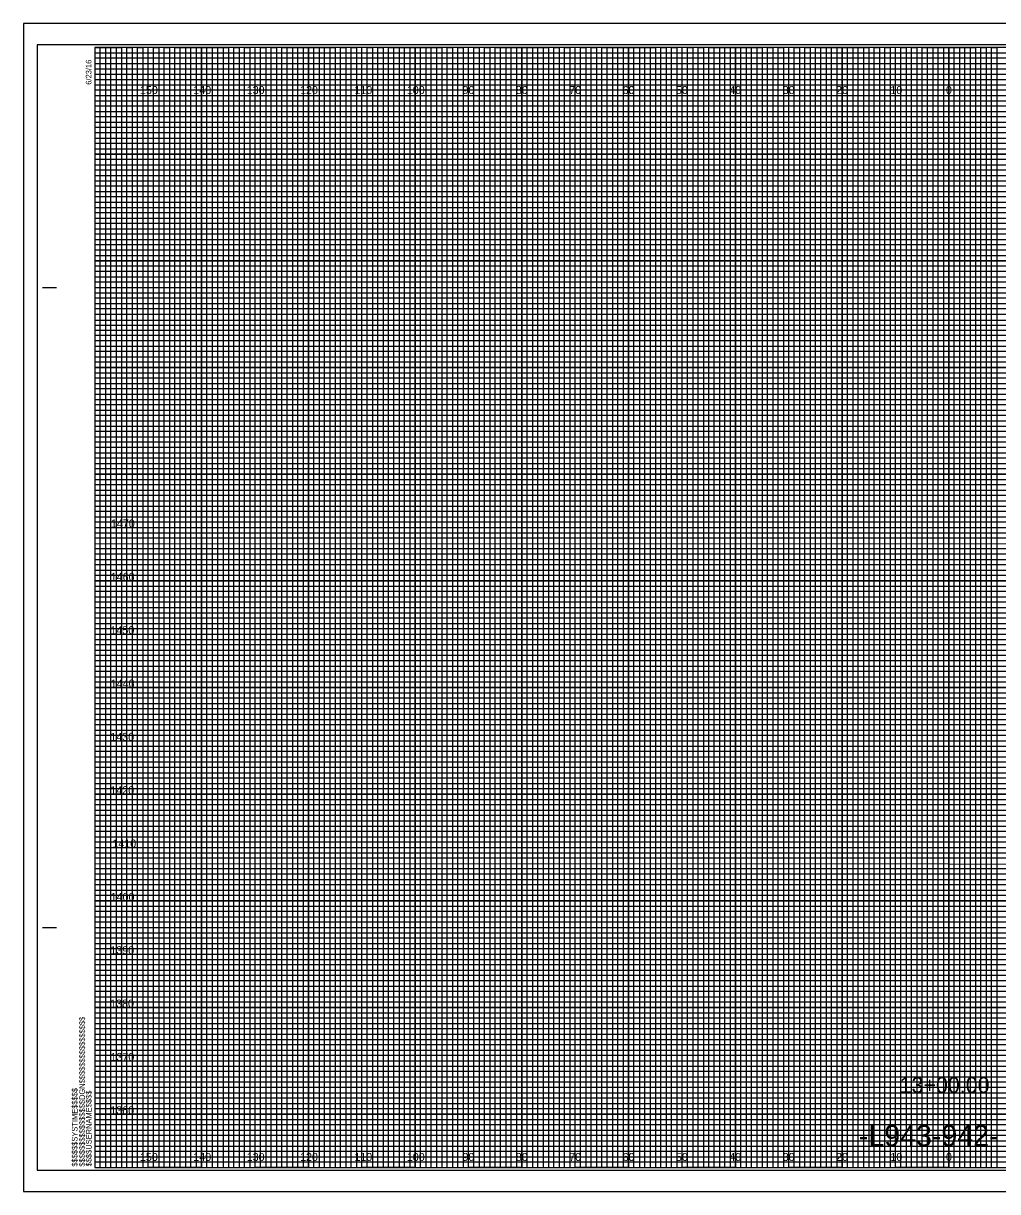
# Model space of a CAD drawing. Extents: x -13 to 323, y -5 to 215.
# Drawn here: x -13.4 to 169.1, y -4.5 to 214.5 of the extents above; entities that cross this region are included whole.
import ezdxf

# ---------------------------------------------------------------- set-up
doc = ezdxf.new("R2010")
doc.units = 0
for name, color, linetype in [('Exist Cross Section Cell', 7, 'Continuous'), ('Exist XS Center Line Elevation Label', 7, 'Continuous'), ('Exist XS Ground Line', 7, 'Continuous'), ('Prop XS EOT Tick Mark', 7, 'Continuous'), ('Prop XS Finish Grade', 7, 'Continuous'), ('Prop XS Finish Grade Earthwork', 7, 'Continuous'), ('Prop XS Finish Grade Pavement', 7, 'Continuous'), ('Prop XS Subgrade Earthwork', 7, 'Continuous'), ('Prop XSC Text', 7, 'Continuous'), ('Scratch_Level_0', 7, 'Continuous'), ('Scratch_Level_5', 7, 'Continuous'), ('Typical Curb CELL', 7, 'Continuous'), ('Typical Guardrail CELL', 7, 'Continuous')]:
    doc.layers.add(name, color=color, linetype=linetype)

msp = doc.modelspace()

# ---------------------------------------------------------------- linework, layer by layer
at = {"layer": 'Exist Cross Section Cell'}
for points in [[(0, 210), (5, 210), (5, 0), (15, 0), (15, 210), (25, 210), (25, 0), (35, 0), (35, 210), (45, 210), (45, 0), (55, 0), (55, 210), (65, 210), (65, 0), (75, 0), (75, 210), (85, 210), (85, 0), (95, 0), (95, 210), (105, 210), (105, 0), (115, 0), (115, 210), (125, 210), (125, 0), (135, 0), (135, 210), (145, 210), (145, 0), (155, 0), (155, 210), (165, 210), (165, 0), (175, 0)], [(0, 205), (275, 205)], [(0, 185), (320, 185), (320, 195), (0, 195)], [(0, 165), (320, 165), (320, 175), (0, 175)], [(0, 145), (320, 145), (320, 155), (0, 155)], [(0, 125), (320, 125), (320, 135), (0, 135)], [(0, 105), (320, 105), (320, 115), (0, 115)], [(0, 85), (320, 85), (320, 95), (0, 95)], [(0, 65), (320, 65), (320, 75), (0, 75)], [(0, 45), (320, 45), (320, 55), (0, 55)], [(0, 25), (320, 25), (320, 35), (0, 35)], [(0, 5), (320, 5), (320, 15), (0, 15)]]:
    msp.add_lwpolyline(points, dxfattribs=at)
at = {"layer": 'Exist XS Center Line Elevation Label'}
for p, q in [((10, 210), (0, 210)), ((10, 0), (10, 210)), ((30, 210), (20, 210)), ((20, 210), (20, 0)), ((30, 0), (30, 210)), ((50, 210), (40, 210)), ((40, 210), (40, 0)), ((50, 0), (50, 210)), ((70, 210), (60, 210)), ((60, 210), (60, 0)), ((70, 0), (70, 210)), ((90, 210), (80, 210)), ((80, 210), (80, 0)), ((90, 0), (90, 210)), ((110, 210), (100, 210)), ((100, 210), (100, 0)), ((110, 0), (110, 210)), ((130, 210), (120, 210)), ((120, 210), (120, 0)), ((130, 0), (130, 210)), ((150, 210), (140, 210)), ((140, 210), (140, 0)), ((150, 0), (150, 210)), ((170, 210), (160, 210)), ((160, 210), (160, 0)), ((20, 0), (10, 0)), ((40, 0), (30, 0)), ((60, 0), (50, 0)), ((80, 0), (70, 0)), ((100, 0), (90, 0)), ((120, 0), (110, 0)), ((140, 0), (130, 0)), ((160, 0), (150, 0))]:
    msp.add_line(p, q, dxfattribs=at)
for points in [[(0, 200), (320, 200), (320, 190), (0, 190)], [(0, 180), (320, 180), (320, 170), (0, 170)], [(0, 160), (320, 160), (320, 150), (0, 150)], [(0, 140), (320, 140), (320, 130), (0, 130)], [(0, 120), (320, 120), (320, 110), (0, 110)], [(0, 100), (320, 100), (320, 90), (0, 90)], [(0, 80), (320, 80), (320, 70), (0, 70)], [(0, 60), (320, 60), (320, 50), (0, 50)], [(0, 40), (320, 40), (320, 30), (0, 30)], [(0, 20), (320, 20), (320, 10), (0, 10)]]:
    msp.add_lwpolyline(points, dxfattribs=at)
at = {"layer": 'Prop XS EOT Tick Mark'}
for p, q in [((10, 0), (10, 210)), ((20, 0), (20, 210)), ((30, 0), (30, 210)), ((40, 0), (40, 210)), ((50, 0), (50, 210)), ((60, 0), (60, 210)), ((70, 0), (70, 210)), ((80, 0), (80, 210)), ((90, 0), (90, 210)), ((100, 0), (100, 210)), ((110, 0), (110, 210)), ((120, 0), (120, 210)), ((130, 0), (130, 210)), ((140, 0), (140, 210)), ((150, 0), (150, 210)), ((160, 0), (160, 210)), ((0, 200), (320, 200)), ((0, 190), (320, 190)), ((0, 180), (320, 180)), ((0, 170), (320, 170)), ((0, 160), (320, 160)), ((0, 150), (320, 150)), ((0, 140), (320, 140)), ((0, 130), (320, 130)), ((0, 120), (320, 120)), ((0, 110), (320, 110)), ((0, 100), (320, 100)), ((0, 90), (320, 90)), ((0, 80), (320, 80)), ((0, 70), (320, 70)), ((0, 60), (320, 60)), ((0, 50), (320, 50)), ((0, 40), (320, 40)), ((0, 30), (320, 30)), ((0, 20), (320, 20)), ((0, 10), (320, 10))]:
    msp.add_line(p, q, dxfattribs=at)
at = {"layer": 'Prop XS Finish Grade Pavement'}
msp.add_lwpolyline([(-13.4, -4.5), (323.3, -4.5), (323.3, 214.5), (-13.4, 214.5)], close=True, dxfattribs=at)
at = {"layer": 'Prop XS Subgrade Earthwork'}
msp.add_lwpolyline([(-10.8, -0.5), (322.4, -0.5), (322.4, 210.5), (-10.8, 210.5)], close=True, dxfattribs=at)
at = {"layer": 'Prop XSC Text'}
for points in [[(0, 0), (1, 0), (1, 210), (2, 210), (2, 0)], [(2, 0), (3, 0), (3, 210), (4, 210), (4, 0)], [(5, 0), (6, 0), (6, 210), (7, 210), (7, 0)], [(7, 0), (8, 0), (8, 210), (9, 210), (9, 0)], [(10, 0), (11, 0), (11, 210), (12, 210), (12, 0)], [(12, 0), (13, 0), (13, 210), (14, 210), (14, 0)], [(15, 0), (16, 0), (16, 210), (17, 210), (17, 0)], [(17, 0), (18, 0), (18, 210), (19, 210), (19, 0)], [(20, 0), (21, 0), (21, 210), (22, 210), (22, 0)], [(22, 0), (23, 0), (23, 210), (24, 210), (24, 0)], [(25, 0), (26, 0), (26, 210), (27, 210), (27, 0)], [(27, 0), (28, 0), (28, 210), (29, 210), (29, 0)], [(30, 0), (31, 0), (31, 210), (32, 210), (32, 0)], [(32, 0), (33, 0), (33, 210), (34, 210), (34, 0)], [(35, 0), (36, 0), (36, 210), (37, 210), (37, 0)], [(37, 0), (38, 0), (38, 210), (39, 210), (39, 0)], [(40, 0), (41, 0), (41, 210), (42, 210), (42, 0)], [(42, 0), (43, 0), (43, 210), (44, 210), (44, 0)], [(45, 0), (46, 0), (46, 210), (47, 210), (47, 0)], [(47, 0), (48, 0), (48, 210), (49, 210), (49, 0)], [(50, 0), (51, 0), (51, 210), (52, 210), (52, 0)], [(52, 0), (53, 0), (53, 210), (54, 210), (54, 0)], [(55, 0), (56, 0), (56, 210), (57, 210), (57, 0)], [(57, 0), (58, 0), (58, 210), (59, 210), (59, 0)], [(60, 0), (61, 0), (61, 210), (62, 210), (62, 0)], [(62, 0), (63, 0), (63, 210), (64, 210), (64, 0)], [(65, 0), (66, 0), (66, 210), (67, 210), (67, 0)], [(67, 0), (68, 0), (68, 210), (69, 210), (69, 0)], [(70, 0), (71, 0), (71, 210), (72, 210), (72, 0)], [(72, 0), (73, 0), (73, 210), (74, 210), (74, 0)], [(75, 0), (76, 0), (76, 210), (77, 210), (77, 0)], [(77, 0), (78, 0), (78, 210), (79, 210), (79, 0)], [(80, 0), (81, 0), (81, 210), (82, 210), (82, 0)], [(82, 0), (83, 0), (83, 210), (84, 210), (84, 0)], [(85, 0), (86, 0), (86, 210), (87, 210), (87, 0)], [(87, 0), (88, 0), (88, 210), (89, 210), (89, 0)], [(90, 0), (91, 0), (91, 210), (92, 210), (92, 0)], [(92, 0), (93, 0), (93, 210), (94, 210), (94, 0)], [(95, 0), (96, 0), (96, 210), (97, 210), (97, 0)], [(97, 0), (98, 0), (98, 210), (99, 210), (99, 0)], [(100, 0), (101, 0), (101, 210), (102, 210), (102, 0)], [(102, 0), (103, 0), (103, 210), (104, 210), (104, 0)], [(105, 0), (106, 0), (106, 210), (107, 210), (107, 0)], [(107, 0), (108, 0), (108, 210), (109, 210), (109, 0)], [(110, 0), (111, 0), (111, 210), (112, 210), (112, 0)], [(112, 0), (113, 0), (113, 210), (114, 210), (114, 0)], [(115, 0), (116, 0), (116, 210), (117, 210), (117, 0)], [(117, 0), (118, 0), (118, 210), (119, 210), (119, 0)], [(120, 0), (121, 0), (121, 210), (122, 210), (122, 0)], [(122, 0), (123, 0), (123, 210), (124, 210), (124, 0)], [(125, 0), (126, 0), (126, 210), (127, 210), (127, 0)], [(127, 0), (128, 0), (128, 210), (129, 210), (129, 0)], [(130, 0), (131, 0), (131, 210), (132, 210), (132, 0)], [(132, 0), (133, 0), (133, 210), (134, 210), (134, 0)], [(135, 0), (136, 0), (136, 210), (137, 210), (137, 0)], [(137, 0), (138, 0), (138, 210), (139, 210), (139, 0)], [(140, 0), (141, 0), (141, 210), (142, 210), (142, 0)], [(142, 0), (143, 0), (143, 210), (144, 210), (144, 0)], [(145, 0), (146, 0), (146, 210), (147, 210), (147, 0)], [(147, 0), (148, 0), (148, 210), (149, 210), (149, 0)], [(150, 0), (151, 0), (151, 210), (152, 210), (152, 0)], [(152, 0), (153, 0), (153, 210), (154, 210), (154, 0)], [(155, 0), (156, 0), (156, 210), (157, 210), (157, 0)], [(157, 0), (158, 0), (158, 210), (159, 210), (159, 0)], [(160, 0), (161, 0), (161, 210), (162, 210), (162, 0)], [(162, 0), (163, 0), (163, 210), (164, 210), (164, 0)], [(165, 0), (166, 0), (166, 210), (167, 210), (167, 0)], [(167, 0), (168, 0), (168, 210), (169, 210), (169, 0)]]:
    msp.add_lwpolyline(points, dxfattribs=at)
at = {"layer": 'Scratch_Level_0'}
for p, q in [((-9.8, 165), (-7.3, 165)), ((-9.7, 165), (-7.2, 165)), ((-9.8, 45), (-7.3, 45)), ((-9.7, 45), (-7.2, 45)), ((0, 0), (0, 0)), ((0, 0), (0, 0)), ((0, 0), (0, 0)), ((0, 0), (0, 0)), ((0, 0), (0, 0)), ((0, 0), (0, 0)), ((0, 0), (0, 0))]:
    msp.add_line(p, q, dxfattribs=at)
msp.add_lwpolyline([(320, 210), (0, 210), (0, 0), (320, 0)], close=True, dxfattribs=at)
at = {"layer": 'Scratch_Level_5'}
for p, q in [((0, 209), (260, 209)), ((260, 207.98), (0, 207.98)), ((0, 207.98), (0, 207)), ((0, 207), (260, 207)), ((260, 205.89), (0, 205.89)), ((0, 205.89), (0, 204)), ((0, 204), (320, 204))]:
    msp.add_line(p, q, dxfattribs=at)
for points in [[(0, 203), (270, 203), (320, 203), (320, 202), (0, 202)], [(0, 201), (320, 201), (320, 199), (0, 199)], [(0, 198), (320, 198), (320, 197), (0, 196.98)], [(0, 196), (320, 196), (320, 194), (0, 194)], [(0, 193), (320, 193), (320, 192), (0, 192)], [(0, 191), (320, 191), (320, 189), (0, 189)], [(0, 188), (320, 188), (320, 187), (0, 187)], [(0, 186), (320, 186), (320, 184), (0, 184)], [(0, 183), (320, 183), (320, 182), (0, 182)], [(0, 181), (320, 181), (320, 179), (0, 179)], [(0, 178), (320, 178), (320, 177), (0, 177)], [(0, 176), (320, 176), (320, 173.95), (320, 173), (320, 172), (0, 172)], [(0, 174), (320, 174), (320, 173), (0, 173)], [(0, 171), (320, 171), (320, 169), (0, 169.03)], [(0, 169.03), (320, 169), (320, 168), (0, 168)], [(0, 167), (320, 167), (320, 166), (0, 166)], [(0, 164), (320, 164), (320, 163), (0, 163)], [(0, 162), (320, 162), (320, 161), (0, 161)], [(-0.07, 158.89), (320, 158.89), (320, 157.88), (-0.07, 157.88)], [(0, 157), (320, 157), (320, 156), (0, 156)], [(0, 154), (320, 154), (320, 153), (0, 153)], [(0, 152), (320, 152), (320, 151), (0, 151)], [(0, 149), (320, 149), (320, 148), (0, 148)], [(0, 147), (320, 147), (320, 146), (0, 146)], [(0, 144), (320, 144), (320, 143), (0, 143)], [(0, 142), (320, 142), (320, 141), (0, 141)], [(0, 139), (320, 139), (319.99, 137.98), (0, 138)], [(0, 137), (320, 137), (320, 136), (0, 136)], [(0, 134), (320, 134), (320, 133), (0, 133)], [(0, 132), (320, 132), (320, 131), (0, 131)], [(0, 129), (320, 129), (320, 128), (0, 128)], [(0, 127), (320, 127), (320, 126), (0, 126)], [(0, 124), (320, 124), (320, 123), (0, 123)], [(0, 122), (320, 122), (320, 121), (0, 121)], [(0, 119), (320, 119), (320, 118), (0, 118)], [(0, 116.99), (320.07, 116.91), (320, 116), (0, 116)], [(0, 114), (320, 114), (320, 113), (0, 113)], [(0, 112), (320, 112), (320, 111), (0, 111)], [(0, 109), (320, 109), (320, 108), (0, 108)], [(0, 107), (320, 107), (320, 106), (0, 106)], [(0, 104), (320, 104), (320, 103), (0, 103)], [(0, 102), (320, 102), (320, 101), (0, 101)], [(0, 99), (320, 99), (320, 98), (0, 98)], [(0, 97), (320, 97), (320, 96), (0, 96)], [(0, 94), (320, 94), (320, 93), (0, 93)], [(0, 92), (320, 92), (320, 91), (0, 91)], [(0, 89), (320, 89), (320, 88), (0, 88)], [(0, 87), (320, 87), (320, 86), (0, 86)], [(0, 84), (320, 84), (320, 83), (0, 83)], [(0, 82), (320, 82), (320, 81), (0, 81)], [(0, 79), (320, 79), (319.99, 77.98), (0, 78)], [(0, 77), (320, 77), (320, 76), (0, 76)], [(0, 74), (320, 74), (320, 73), (0, 73)], [(0, 72), (320, 72), (320, 71), (0, 71)], [(0, 69), (320, 69), (320, 68), (0, 68)], [(0, 67), (320, 67), (320, 66), (0, 66)], [(0, 64), (320, 64), (320, 63), (0, 63)], [(0, 62), (320, 62), (320, 61), (0, 61)], [(0, 59), (320, 59), (320, 58), (0, 58)], [(0, 56.99), (320.07, 56.91), (320, 56), (0, 56)], [(0, 54), (320, 54), (320, 53), (0, 53)], [(0, 52), (320, 52), (320, 51), (0, 51)], [(0, 49), (320, 49), (320, 48), (0, 48)], [(0, 47), (320, 47), (320, 46), (0, 46)], [(0, 44), (320, 44), (320, 43), (0, 43)], [(0, 42), (320, 42), (320, 41), (0, 41)], [(0, 39), (320, 39), (320, 38), (0, 38)], [(0, 37), (320, 37), (320, 36), (0, 36)], [(0, 34), (320, 34), (320, 33), (0, 33)], [(0, 32), (320, 32), (320, 31), (0, 31)], [(0, 29), (320, 29), (320, 28), (0, 28)], [(0, 27), (320, 27), (320, 26), (0, 26)], [(0, 24), (320, 24), (320, 23), (0, 23)], [(0, 22), (320, 22), (320, 21), (0, 21)], [(0, 19), (320, 19), (320, 18), (0, 18)], [(0, 17), (320, 17), (320, 16), (0, 16)], [(0, 14), (320, 14), (320, 13), (0, 13)], [(0, 12), (320, 12), (320, 11), (0, 11)], [(0, 9), (320, 9), (320, 8), (0, 8)], [(0, 7), (320, 7), (320, 6), (0, 6)], [(0, 4), (320, 4), (320, 3), (0, 3)], [(0, 2), (320, 2), (320, 1), (0, 1)]]:
    msp.add_lwpolyline(points, dxfattribs=at)
at = {"layer": 'Typical Curb CELL'}
for p, q in [((323.3, 214.5), (-13.4, 214.5)), ((-13.4, 214.5), (-13.4, -4.5)), ((-13.4, -4.5), (323.3, -4.5))]:
    msp.add_line(p, q, dxfattribs=at)

# ---------------------------------------------------------------- texts
at = {"layer": 'Exist XS Ground Line'}
for s, p in [('150', (8.44, 201.25)), ('140', (18.44, 201.25)), ('130', (28.44, 201.25)), ('120', (38.44, 201.25)), ('110', (48.62, 201.25)), ('100', (58.44, 201.25)), ('90', (68.86, 201.25)), ('80', (78.86, 201.25)), ('70', (88.86, 201.25)), ('60', (98.86, 201.25)), ('50', (108.86, 201.25)), ('40', (118.86, 201.25)), ('30', (128.86, 201.25)), ('20', (138.86, 201.25)), ('10', (149.04, 201.25)), ('0', (159.45, 201.25)), ('0', (159.45, 201.25)), ('150', (8.44, 1.25)), ('140', (18.44, 1.25)), ('130', (28.44, 1.25)), ('120', (38.44, 1.25)), ('110', (48.62, 1.25)), ('100', (58.44, 1.25)), ('90', (68.86, 1.25)), ('80', (78.86, 1.25)), ('70', (88.86, 1.25)), ('60', (98.86, 1.25)), ('50', (108.86, 1.25)), ('40', (118.86, 1.25)), ('30', (128.86, 1.25)), ('20', (138.86, 1.25)), ('10', (149.04, 1.25)), ('0', (159.45, 1.25)), ('0', (159.45, 1.25))]:
    msp.add_text(s, height=1.5, dxfattribs=at).set_placement(p)
at = {"layer": 'Prop XS Finish Grade'}
for s, p in [('1470', (3, 120)), ('1460', (2.97, 110)), ('1450', (2.92, 100)), ('1440', (2.97, 90)), ('1430', (2.89, 80)), ('1420', (2.9, 70)), ('1410', (3.28, 60)), ('1400', (2.95, 50)), ('1390', (2.89, 40)), ('1380', (2.86, 30)), ('1370', (2.92, 20)), ('1360', (2.89, 10))]:
    msp.add_text(s, height=1.5, dxfattribs=at).set_placement(p)
at = {"layer": 'Prop XS Finish Grade Earthwork'}
msp.add_text('13+00.00', height=3, dxfattribs=at).set_placement((150.77, 13.99))
at = {"layer": 'Scratch_Level_0'}
for s, p in [('6/23/16', (-0.65, 203)), ('$$$$$$$$$$$$$$$$DGN$$$$$$$$$$$$$$$$', (-1.88, 0.18)), ('$$$$$$SYSTIME$$$$$', (-3.26, 0.18)), ('$$$$USERNAME$$$$', (-0.62, 0.23))]:
    msp.add_text(s, height=1.05, rotation=90, dxfattribs=at).set_placement(p)
at = {"layer": 'Typical Guardrail CELL'}
msp.add_text('-L943-942-', height=4, dxfattribs=at).set_placement((143.13, 4))

doc.saveas('drawing.dxf')
